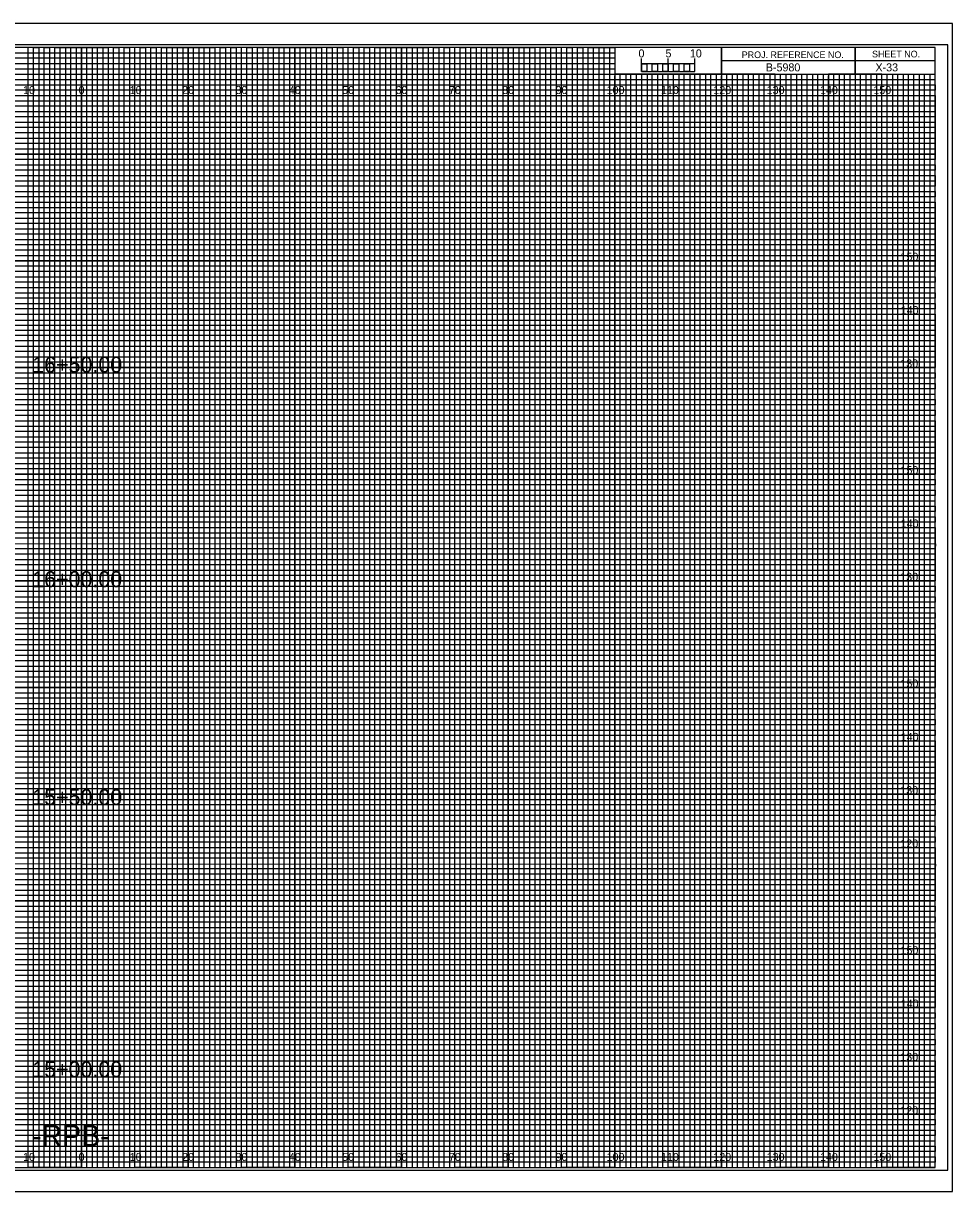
# Model space of a CAD drawing. Extents: x -13 to 323, y -5 to 1094.
# Drawn here: x 149.1 to 323.3, y -4.5 to 214.5 of the extents above; entities that cross this region are included whole.
import ezdxf

# ---------------------------------------------------------------- set-up
doc = ezdxf.new("R2010")
doc.units = 0
for name, color, linetype in [('Exist Cross Section Cell', 7, 'Continuous'), ('Exist XS Center Line Elevation Label', 7, 'Continuous'), ('Exist XS Ground Line', 7, 'Continuous'), ('Prop CMT Concrete Structures', 7, 'Continuous'), ('Prop CMT Guardrail Graphics', 7, 'Continuous'), ('Prop CMT Pvmt Course 1', 7, 'Continuous'), ('Prop CMT Pvmt Course 1 CG', 7, 'Continuous'), ('Prop CMT Pvmt Course 2', 7, 'Continuous'), ('Prop CMT Pvmt Course 3', 7, 'Continuous'), ('Prop CMT Pvmt Surface', 7, 'Continuous'), ('Prop CMT Pvmt Surface Shoulder', 7, 'Continuous'), ('Prop CMT Shld Paved Course 1', 7, 'Continuous'), ('Prop CMT Shld Paved Course 2', 7, 'Continuous'), ('Prop CMT Shld Paved Course 3', 7, 'Continuous'), ('Prop CMT Slope Grass', 7, 'Continuous'), ('Prop CMT Subgrade Earthwork', 7, 'Continuous'), ('Scratch_Level_1', 7, 'Continuous')]:
    doc.layers.add(name, color=color, linetype=linetype)

msp = doc.modelspace()

# ---------------------------------------------------------------- linework, layer by layer
at = {"layer": 'Exist XS Center Line Elevation Label'}
for points in [[(145, 0), (155, 0), (155, 210), (165, 210), (165, 0), (175, 0), (175, 210), (185, 210), (185, 0), (195, 0), (195, 210), (205, 210), (205, 0), (215, 0), (215, 210), (225, 210), (225, 0), (235, 0), (235, 210), (245, 210), (245, 0), (255, 0), (255, 210), (259.93, 210), (260, 210), (260, 205), (264.99, 205), (264.99, 0), (275, 0), (275, 205), (285, 205), (285, 0), (295, 0), (295, 205), (305, 205), (305, 0), (315, 0), (315, 205)], [(0, 205), (275, 205)], [(0, 185), (320, 185), (320, 195), (0, 195)], [(0, 165), (320, 165), (320, 175), (0, 175)], [(0, 145), (320, 145), (320, 155), (0, 155)], [(0, 125), (320, 125), (320, 135), (0, 135)], [(0, 105), (320, 105), (320, 115), (0, 115)], [(0, 85), (320, 85), (320, 95), (0, 95)], [(0, 65), (320, 65), (320, 75), (0, 75)], [(0, 45), (320, 45), (320, 55), (0, 55)], [(0, 25), (320, 25), (320, 35), (0, 35)], [(0, 5), (320, 5), (320, 15), (0, 15)]]:
    msp.add_lwpolyline(points, dxfattribs=at)
at = {"layer": 'Exist XS Ground Line'}
for p, q in [((150, 210), (140, 210)), ((150, 0), (150, 210)), ((170, 210), (160, 210)), ((160, 210), (160, 0)), ((170, 0), (170, 210)), ((190, 210), (180, 210)), ((180, 210), (180, 0)), ((190, 0), (190, 210)), ((210, 210), (200, 210)), ((200, 210), (200, 0)), ((210, 0), (210, 210)), ((230, 210), (220, 210)), ((220, 210), (220, 0)), ((230, 0), (230, 210)), ((250, 210), (240, 210)), ((240, 210), (240, 0)), ((250, 0), (250, 210)), ((260, 210), (260, 0)), ((270, 0), (270, 205)), ((290, 205), (280, 205)), ((280, 205), (280, 0)), ((290, 0), (290, 205)), ((310, 205), (300, 205)), ((300, 205), (300, 0)), ((310, 0), (310, 205)), ((160, 0), (150, 0)), ((180, 0), (170, 0)), ((200, 0), (190, 0)), ((220, 0), (210, 0)), ((240, 0), (230, 0)), ((260, 0), (250, 0)), ((280, 0), (270, 0)), ((300, 0), (290, 0)), ((320, 0), (310, 0)), ((320, 0), (320, 0))]:
    msp.add_line(p, q, dxfattribs=at)
for points in [[(0, 200), (320, 200), (320, 190), (0, 190)], [(0, 180), (320, 180), (320, 170), (0, 170)], [(0, 160), (320, 160), (320, 150), (0, 150)], [(0, 140), (320, 140), (320, 130), (0, 130)], [(0, 120), (320, 120), (320, 110), (0, 110)], [(0, 100), (320, 100), (320, 90), (0, 90)], [(0, 80), (320, 80), (320, 70), (0, 70)], [(0, 60), (320, 60), (320, 50), (0, 50)], [(0, 40), (320, 40), (320, 30), (0, 30)], [(0, 20), (320, 20), (320, 10), (0, 10)]]:
    msp.add_lwpolyline(points, dxfattribs=at)
at = {"layer": 'Prop CMT Pvmt Course 2'}
for p, q in [((265, 205.49), (265, 207.9)), ((265, 206.9), (265, 207.9)), ((270, 205.49), (270, 207.9)), ((275, 205.49), (275, 207.9)), ((275, 206.9), (275, 207.9))]:
    msp.add_line(p, q, dxfattribs=at)
for points in [[(275, 206.9), (265, 206.9), (265, 205.49), (275, 205.49)], [(265, 206.9), (266, 206.9), (266, 205.49), (265, 205.49)], [(267, 206.9), (268, 206.9), (268, 205.49), (267, 205.49)], [(269, 206.9), (270, 206.9), (270, 205.49), (269, 205.49)], [(271, 206.9), (272, 206.9), (272, 205.49), (271, 205.49)], [(273, 206.9), (274, 206.9), (274, 205.49), (273, 205.49)]]:
    msp.add_lwpolyline(points, close=True, dxfattribs=at)
at = {"layer": 'Prop CMT Pvmt Course 3'}
msp.add_lwpolyline([(-13.4, -4.5), (323.3, -4.5), (323.3, 214.5), (-13.4, 214.5)], close=True, dxfattribs=at)
at = {"layer": 'Prop CMT Pvmt Surface'}
for p, q in [((150, 0), (150, 210)), ((160, 0), (160, 210)), ((170, 0), (170, 210)), ((180, 0), (180, 210)), ((190, 0), (190, 210)), ((200, 0), (200, 210)), ((210, 0), (210, 210)), ((220, 0), (220, 210)), ((230, 0), (230, 210)), ((240, 0), (240, 210)), ((250, 0), (250, 210)), ((260, 0), (260, 204.69)), ((270, 0), (270, 204.69)), ((280, 0), (280, 204.69)), ((290, 0), (290, 204.69)), ((300, 0), (300, 204.69)), ((310, 0), (310, 204.69)), ((0, 200), (320, 200)), ((0, 190), (320, 190)), ((0, 180), (320, 180)), ((0, 170), (320, 170)), ((0, 160), (320, 160)), ((0, 150), (320, 150)), ((0, 140), (320, 140)), ((0, 130), (320, 130)), ((0, 120), (320, 120)), ((0, 110), (320, 110)), ((0, 100), (320, 100)), ((0, 90), (320, 90)), ((0, 80), (320, 80)), ((0, 70), (320, 70)), ((0, 60), (320, 60)), ((0, 50), (320, 50)), ((0, 40), (320, 40)), ((0, 30), (320, 30)), ((0, 20), (320, 20)), ((0, 10), (320, 10))]:
    msp.add_line(p, q, dxfattribs=at)
at = {"layer": 'Prop CMT Pvmt Surface Shoulder'}
for p, q in [((323.3, 214.5), (-13.4, 214.5)), ((-13.4, -4.5), (323.3, -4.5))]:
    msp.add_line(p, q, dxfattribs=at)
at = {"layer": 'Prop CMT Shld Paved Course 1'}
for p, q in [((0, 209), (260, 209)), ((260, 209), (260, 207.98)), ((260, 207.98), (0, 207.98)), ((0, 207), (260, 207)), ((260, 205.89), (0, 205.89)), ((260, 207), (260, 205.89)), ((0, 204), (320, 204))]:
    msp.add_line(p, q, dxfattribs=at)
for points in [[(0, 203), (270, 203), (320, 203), (320, 202), (0, 202)], [(0, 201), (320, 201), (320, 199), (0, 199)], [(0, 198), (320, 198), (320, 197), (0, 196.98)], [(0, 196), (320, 196), (320, 194), (0, 194)], [(0, 193), (320, 193), (320, 192), (0, 192)], [(0, 191), (320, 191), (320, 189), (0, 189)], [(0, 188), (320, 188), (320, 187), (0, 187)], [(0, 186), (320, 186), (320, 184), (0, 184)], [(0, 183), (320, 183), (320, 182), (0, 182)], [(0, 181), (320, 181), (320, 179), (0, 179)], [(0, 178), (320, 178), (320, 177), (0, 177)], [(0, 176), (320, 176), (320, 173.95), (320, 173), (320, 172), (0, 172)], [(0, 174), (320, 174), (320, 173), (0, 173)], [(0, 171), (320, 171), (320, 169), (0, 169.03)], [(0, 169.03), (320, 169), (320, 168), (0, 168)], [(0, 167), (320, 167), (320, 166), (0, 166)], [(0, 164), (320, 164), (320, 163), (0, 163)], [(0, 162), (320, 162), (320, 161), (0, 161)], [(-0.07, 158.89), (320, 158.89), (320, 157.88), (-0.07, 157.88)], [(0, 157), (320, 157), (320, 156), (0, 156)], [(0, 154), (320, 154), (320, 153), (0, 153)], [(0, 152), (320, 152), (320, 151), (0, 151)], [(0, 149), (320, 149), (320, 148), (0, 148)], [(0, 147), (320, 147), (320, 146), (0, 146)], [(0, 144), (320, 144), (320, 143), (0, 143)], [(0, 142), (320, 142), (320, 141), (0, 141)], [(0, 139), (320, 139), (319.99, 137.98), (0, 138)], [(0, 137), (320, 137), (320, 136), (0, 136)], [(0, 134), (320, 134), (320, 133), (0, 133)], [(0, 132), (320, 132), (320, 131), (0, 131)], [(0, 129), (320, 129), (320, 128), (0, 128)], [(0, 127), (320, 127), (320, 126), (0, 126)], [(0, 124), (320, 124), (320, 123), (0, 123)], [(0, 122), (320, 122), (320, 121), (0, 121)], [(0, 119), (320, 119), (320, 118), (0, 118)], [(0, 116.99), (320.07, 116.91), (320, 116), (0, 116)], [(0, 114), (320, 114), (320, 113), (0, 113)], [(0, 112), (320, 112), (320, 111), (0, 111)], [(0, 109), (320, 109), (320, 108), (0, 108)], [(0, 107), (320, 107), (320, 106), (0, 106)], [(0, 104), (320, 104), (320, 103), (0, 103)], [(0, 102), (320, 102), (320, 101), (0, 101)], [(0, 99), (320, 99), (320, 98), (0, 98)], [(0, 97), (320, 97), (320, 96), (0, 96)], [(0, 94), (320, 94), (320, 93), (0, 93)], [(0, 92), (320, 92), (320, 91), (0, 91)], [(0, 89), (320, 89), (320, 88), (0, 88)], [(0, 87), (320, 87), (320, 86), (0, 86)], [(0, 84), (320, 84), (320, 83), (0, 83)], [(0, 82), (320, 82), (320, 81), (0, 81)], [(0, 79), (320, 79), (319.99, 77.98), (0, 78)], [(0, 77), (320, 77), (320, 76), (0, 76)], [(0, 74), (320, 74), (320, 73), (0, 73)], [(0, 72), (320, 72), (320, 71), (0, 71)], [(0, 69), (320, 69), (320, 68), (0, 68)], [(0, 67), (320, 67), (320, 66), (0, 66)], [(0, 64), (320, 64), (320, 63), (0, 63)], [(0, 62), (320, 62), (320, 61), (0, 61)], [(0, 59), (320, 59), (320, 58), (0, 58)], [(0, 56.99), (320.07, 56.91), (320, 56), (0, 56)], [(0, 54), (320, 54), (320, 53), (0, 53)], [(0, 52), (320, 52), (320, 51), (0, 51)], [(0, 49), (320, 49), (320, 48), (0, 48)], [(0, 47), (320, 47), (320, 46), (0, 46)], [(0, 44), (320, 44), (320, 43), (0, 43)], [(0, 42), (320, 42), (320, 41), (0, 41)], [(0, 39), (320, 39), (320, 38), (0, 38)], [(0, 37), (320, 37), (320, 36), (0, 36)], [(0, 34), (320, 34), (320, 33), (0, 33)], [(0, 32), (320, 32), (320, 31), (0, 31)], [(0, 29), (320, 29), (320, 28), (0, 28)], [(0, 27), (320, 27), (320, 26), (0, 26)], [(0, 24), (320, 24), (320, 23), (0, 23)], [(0, 22), (320, 22), (320, 21), (0, 21)], [(0, 19), (320, 19), (320, 18), (0, 18)], [(0, 17), (320, 17), (320, 16), (0, 16)], [(0, 14), (320, 14), (320, 13), (0, 13)], [(0, 12), (320, 12), (320, 11), (0, 11)], [(0, 9), (320, 9), (320, 8), (0, 8)], [(0, 7), (320, 7), (320, 6), (0, 6)], [(0, 4), (320, 4), (320, 3), (0, 3)], [(0, 2), (320, 2), (320, 1), (0, 1)]]:
    msp.add_lwpolyline(points, dxfattribs=at)
at = {"layer": 'Prop CMT Shld Paved Course 2'}
for p, q in [((305, 210), (305, 205)), ((305, 205), (305, 210)), ((280, 207.5), (280, 205)), ((320, 207.49), (280, 207.49)), ((280, 205), (320, 205))]:
    msp.add_line(p, q, dxfattribs=at)
for points in [[(320, 210), (0, 210), (0, 0), (320, 0)], [(280, 210), (260, 210), (260, 205.03), (280, 205.03)], [(320, 210), (280, 210), (280, 205), (320, 205)]]:
    msp.add_lwpolyline(points, close=True, dxfattribs=at)
at = {"layer": 'Prop CMT Shld Paved Course 3'}
for p, q in [((267, 205), (266.01, 205)), ((266.01, 205), (266.01, 0)), ((267, 0), (267, 205)), ((269, 205), (268, 205)), ((268, 205), (268, 0)), ((269, 0), (269, 205)), ((266.01, 0), (265, 0)), ((268, 0), (267, 0))]:
    msp.add_line(p, q, dxfattribs=at)
for points in [[(150, 0), (151, 0), (151, 210), (152, 210), (152, 0)], [(152, 0), (153, 0), (153, 210), (154, 210), (154, 0)], [(155, 0), (156, 0), (156, 210), (157, 210), (157, 0)], [(157, 0), (158, 0), (158, 210), (159, 210), (159, 0)], [(160, 0), (161, 0), (161, 210), (162, 210), (162, 0)], [(162, 0), (163, 0), (163, 210), (164, 210), (164, 0)], [(165, 0), (166, 0), (166, 210), (167, 210), (167, 0)], [(167, 0), (168, 0), (168, 210), (169, 210), (169, 0)], [(170, 0), (171, 0), (171, 210), (172, 210), (172, 0)], [(172, 0), (173, 0), (173, 210), (174, 210), (174, 0)], [(175, 0), (176, 0), (176, 210), (177, 210), (177, 0)], [(177, 0), (178, 0), (178, 210), (179, 210), (179, 0)], [(180, 0), (181, 0), (181, 210), (182, 210), (182, 0)], [(182, 0), (183, 0), (183, 210), (184, 210), (184, 0)], [(185, 0), (186, 0), (186, 210), (187, 210), (187, 0)], [(187, 0), (188, 0), (188, 210), (189, 210), (189, 0)], [(190, 0), (191, 0), (191, 210), (192, 210), (192, 0)], [(192, 0), (193, 0), (193, 210), (194, 210), (194, 0)], [(195, 0), (196, 0), (196, 210), (197, 210), (197, 0)], [(197, 0), (198, 0), (198, 210), (199, 210), (199, 0)], [(200, 0), (201, 0), (201, 210), (202, 210), (202, 0)], [(202, 0), (203, 0), (203, 210), (204, 210), (204, 0)], [(205, 0), (206, 0), (206, 210), (207, 210), (207, 0)], [(207, 0), (208, 0), (208, 210), (209, 210), (209, 0)], [(210, 0), (211, 0), (211, 210), (212, 210), (212, 0)], [(212, 0), (213, 0), (213, 210), (214, 210), (214, 0)], [(215, 0), (216, 0), (216, 210), (217, 210), (217, 0)], [(217, 0), (218, 0), (218, 210), (219, 210), (219, 0)], [(220, 0), (221, 0), (221, 210), (222, 210), (222, 0)], [(222, 0), (223, 0), (223, 210), (224, 210), (224, 0)], [(225, 0), (226, 0), (226, 210), (227, 210), (227, 0)], [(227, 0), (228, 0), (228, 210), (229, 210), (229, 0)], [(230, 0), (231, 0), (231, 210), (232, 210), (232, 0)], [(232, 0), (233, 0), (233, 210), (234, 210), (234, 0)], [(235, 0), (236, 0), (236, 210), (237, 210), (237, 0)], [(237, 0), (238, 0), (238, 210), (239, 210), (239, 0)], [(240, 0), (241, 0), (241, 210), (242, 210), (242, 0)], [(242, 0), (243, 0), (243, 210), (244, 210), (244, 0)], [(245, 0), (246, 0), (246, 210), (247, 210), (247, 0)], [(247, 0), (248, 0), (248, 210), (249, 210), (249, 0)], [(250, 0), (251, 0), (251, 210), (252, 210), (252, 0)], [(252, 0), (253, 0), (253, 210), (254, 210), (254, 0)], [(255, 0), (256, 0), (256, 210), (257, 210), (257, 0)], [(257, 0), (258, 0), (258, 210), (259, 210), (259, 0)], [(260, 0), (261, 0), (261, 205), (262.02, 205), (262.02, 0)], [(262, 0), (263, 0), (263, 205), (263.99, 205), (263.99, 0)], [(270, 0), (270.98, 0), (270.98, 205), (272, 205), (272, 0)], [(272, 0), (273, 0), (273, 205), (274.05, 205), (274.05, 0)], [(275, 0), (276, 0), (276, 205), (277, 205), (277, 0)], [(277, 0), (278, 0), (278, 205), (279, 205), (279, 0)], [(280, 0), (281, 0), (281, 205), (282, 205), (282, 0)], [(282, 0), (283, 0), (283, 205), (284, 205), (284, 0)], [(285, 0), (286, 0), (286, 205), (287, 205), (287, 0)], [(287, 0), (288, 0), (288, 205), (289, 205), (289, 0)], [(290, 0), (291, 0), (291, 205), (292, 205), (292, 0)], [(292, 0), (293, 0), (293, 205), (294, 205), (294, 0)], [(295, 0), (296, 0), (296, 205), (297, 205), (297, 0)], [(297, 0), (298, 0), (298, 205), (299, 205), (299, 0)], [(300, 0), (301, 0), (301, 205), (302, 205), (302, 0)], [(302, 0), (303, 0), (303, 205), (304, 205), (304, 0)], [(305, 0), (306, 0), (306, 205), (307, 205), (307, 0)], [(307, 0), (308, 0), (308, 205), (309, 205), (309, 0)], [(310, 0), (311, 0), (311, 205), (312, 205), (312, 0)], [(312, 0), (313, 0), (313, 205), (314, 205), (314, 0)], [(315, 0), (316, 0), (316, 205), (317, 205), (317, 0)], [(317, 0), (318, 0), (318, 205), (319, 205), (319, 0)]]:
    msp.add_lwpolyline(points, dxfattribs=at)
at = {"layer": 'Prop CMT Subgrade Earthwork'}
msp.add_lwpolyline([(-10.8, -0.5), (322.4, -0.5), (322.4, 210.5), (-10.8, 210.5)], close=True, dxfattribs=at)

# ---------------------------------------------------------------- texts
at = {"layer": 'Exist Cross Section Cell'}
for s, p in [('10', (149.04, 201.25)), ('0', (159.45, 201.25)), ('0', (159.45, 201.25)), ('10', (169.04, 201.25)), ('20', (178.86, 201.25)), ('30', (188.86, 201.25)), ('40', (198.86, 201.25)), ('50', (208.86, 201.25)), ('60', (218.86, 201.25)), ('70', (228.86, 201.25)), ('80', (238.86, 201.25)), ('90', (248.86, 201.25)), ('100', (258.44, 201.25)), ('110', (268.62, 201.25)), ('120', (278.44, 201.25)), ('130', (288.44, 201.25)), ('140', (298.44, 201.25)), ('150', (308.44, 201.25)), ('10', (149.04, 1.25)), ('0', (159.45, 1.25)), ('0', (159.45, 1.25)), ('10', (169.04, 1.25)), ('20', (178.86, 1.25)), ('30', (188.86, 1.25)), ('40', (198.86, 1.25)), ('50', (208.86, 1.25)), ('60', (218.86, 1.25)), ('70', (228.86, 1.25)), ('80', (238.86, 1.25)), ('90', (248.86, 1.25)), ('100', (258.44, 1.25)), ('110', (268.62, 1.25)), ('120', (278.44, 1.25)), ('130', (288.44, 1.25)), ('140', (298.44, 1.25)), ('150', (308.44, 1.25))]:
    msp.add_text(s, height=1.5, dxfattribs=at).set_placement(p)
at = {"layer": 'Prop CMT Concrete Structures'}
msp.add_text('-RPB-', height=4, dxfattribs=at).set_placement((150.72, 4))
at = {"layer": 'Prop CMT Guardrail Graphics'}
msp.add_text('X-33', height=1.5, dxfattribs=at).set_placement((308.83, 205.5))
at = {"layer": 'Prop CMT Pvmt Course 1'}
for s, p in [('150', (313.52, 170)), ('140', (313.57, 160)), ('130', (313.49, 150)), ('150', (313.52, 130)), ('140', (313.57, 120)), ('130', (313.49, 110)), ('150', (313.52, 90)), ('140', (313.57, 80)), ('130', (313.49, 70)), ('120', (313.5, 60)), ('150', (313.52, 40)), ('140', (313.57, 30)), ('130', (313.49, 20)), ('120', (313.5, 10))]:
    msp.add_text(s, height=1.5, dxfattribs=at).set_placement(p)
at = {"layer": 'Prop CMT Pvmt Course 1 CG'}
for s, p in [('5', (269.47, 208.12)), ('10', (274.04, 208.12))]:
    msp.add_text(s, height=1.5, dxfattribs=at).set_placement(p)
at = {"layer": 'Prop CMT Pvmt Course 2'}
msp.add_text('0', height=1.5, dxfattribs=at).set_placement((264.41, 208.12))
at = {"layer": 'Prop CMT Shld Paved Course 2'}
for s, p in [('PROJ. REFERENCE NO.', (283.77, 207.99)), ('SHEET NO.', (308.19, 208.12))]:
    msp.add_text(s, height=1.25, dxfattribs=at).set_placement(p)
at = {"layer": 'Prop CMT Slope Grass'}
for s, p in [('16+50.00', (150.77, 149.03)), ('16+00.00', (150.77, 108.81)), ('15+50.00', (150.77, 67.96)), ('15+00.00', (150.77, 16.93))]:
    msp.add_text(s, height=3, dxfattribs=at).set_placement(p)
at = {"layer": 'Scratch_Level_1'}
msp.add_text('B-5980', height=1.5, dxfattribs=at).set_placement((288.28, 205.5))

doc.saveas('drawing.dxf')
